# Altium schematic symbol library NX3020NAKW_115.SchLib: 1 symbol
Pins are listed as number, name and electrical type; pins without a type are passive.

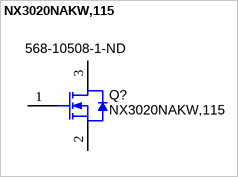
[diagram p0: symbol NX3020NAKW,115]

## NX3020NAKW,115
designator Q?  Supplier Part Number: 568-10508-1-ND
MOSFET N-CH 30V 180MA SOT323; Manufacturer: NXP Semiconductors; Alternate Manufacturer: None; U/M: EA; ChType: N; Value: 60V; Value1: 1.6 ohm; Rdson45_ohm: 1.6; Value2: ? nC; Vgs_V: 2.1; IdsMax_A: 0.31; Rds On (Max) @ Id, Vgs: 4.5 Ohm @ 100mA, 10V; FET Type: MOSFET N-Channel, Metal Oxide; Gate Charge (Qg) @ Vgs: 0.44nC @ 4.5V; Input Capacitance (Ciss) @ Vds: 48pF @ 10V; Power - Max: 260mW; Vgs(th) (Max) @ Id: 1.5V @ 250µA; Current - Continuous Drain (Id) @ 25°C: 180mA (Ta); FET Feature: Logic Level Gate
footprint SOT-323
pins: 1 G, 2 S, 3 D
